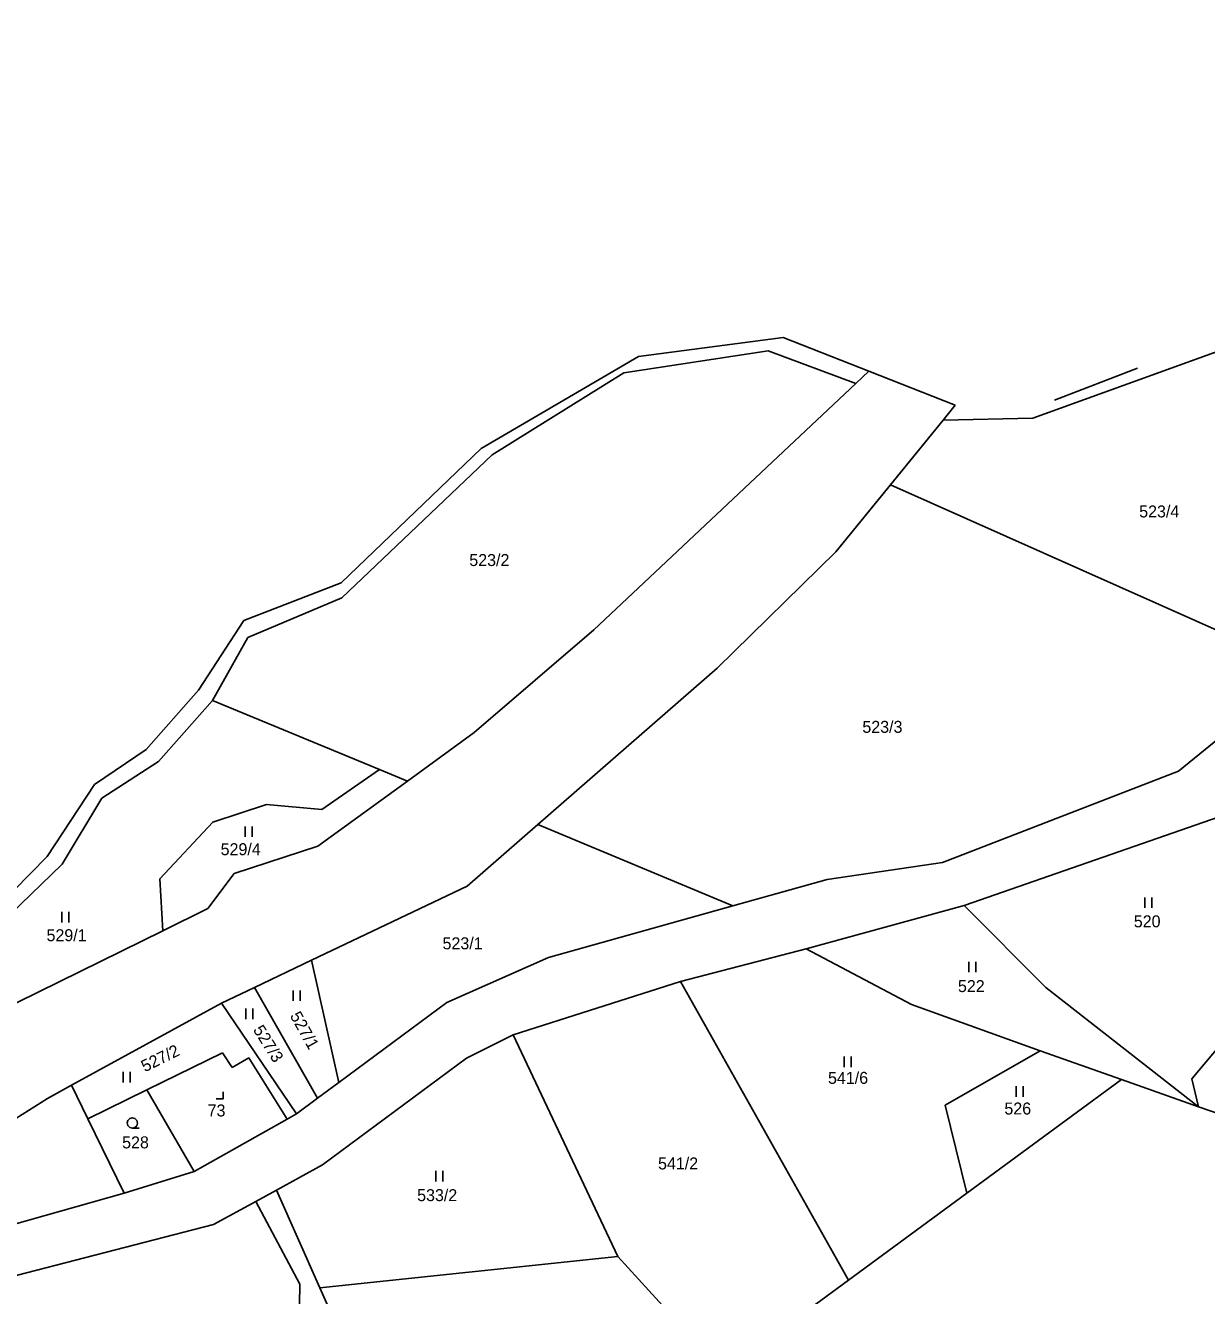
# Model space of a CAD drawing. Extents: x -580551 to -575069, y -1073031 to -1067931.
# Drawn here: x -578084.3 to -577916.6, y -1070422.6 to -1070242.2 of the extents above; entities that cross this region are included whole.
import ezdxf

# ---------------------------------------------------------------- set-up
doc = ezdxf.new("R2010")
doc.units = 0
for name, color, linetype in [('Druh pozemku', 7, 'Continuous'), ('Katastrální hranice', 7, 'Continuous'), ('Parcela', 7, 'Continuous'), ('Parcelní číslo', 7, 'Continuous'), ('Parcelní číslo_stavba', 7, 'Continuous'), ('SR - hranice státu', 7, 'Continuous'), ('Vrstva 6', 7, 'Continuous')]:
    doc.layers.add(name, color=color, linetype=linetype)

msp = doc.modelspace()

# ---------------------------------------------------------------- linework, layer by layer
at = {"layer": 'Druh pozemku'}
for p, q in [((-578053.09, -1070355.96), (-578053.09, -1070357.46)), ((-578052.09, -1070357.46), (-578052.09, -1070355.96)), ((-577925.41, -1070366.04), (-577925.41, -1070367.54)), ((-577924.41, -1070367.54), (-577924.41, -1070366.04)), ((-578079.11, -1070368.1), (-578079.11, -1070369.6)), ((-578078.11, -1070369.6), (-578078.11, -1070368.1)), ((-577950.39, -1070375.17), (-577950.39, -1070376.67)), ((-577949.39, -1070376.67), (-577949.39, -1070375.17)), ((-578046.26, -1070379.24), (-578046.26, -1070380.74)), ((-578045.26, -1070380.74), (-578045.26, -1070379.24)), ((-578052.98, -1070381.83), (-578052.98, -1070383.33)), ((-578051.98, -1070383.33), (-578051.98, -1070381.83)), ((-577968.09, -1070388.64), (-577968.09, -1070390.14)), ((-577967.09, -1070390.14), (-577967.09, -1070388.64)), ((-578070.39, -1070390.8), (-578070.39, -1070392.3)), ((-578069.39, -1070392.3), (-578069.39, -1070390.8)), ((-577943.68, -1070392.85), (-577943.68, -1070394.35)), ((-577942.68, -1070394.35), (-577942.68, -1070392.85)), ((-578026.05, -1070404.85), (-578026.05, -1070406.35)), ((-578025.05, -1070406.35), (-578025.05, -1070404.85))]:
    msp.add_line(p, q, dxfattribs=at)
for points in [[(-578057.21, -1070394.62), (-578056.21, -1070394.62), (-578056.21, -1070393.62)], [(-578069.1, -1070398.8), (-578069.48, -1070398.7), (-578069.75, -1070398.43), (-578069.85, -1070398.06), (-578069.75, -1070397.69), (-578069.48, -1070397.42), (-578069.11, -1070397.32), (-578068.74, -1070397.42), (-578068.47, -1070397.69), (-578068.37, -1070398.07), (-578068.47, -1070398.45), (-578068.74, -1070398.72), (-578069.12, -1070398.82), (-578068.12, -1070398.82)]]:
    msp.add_lwpolyline(points, dxfattribs=at)
at = {"layer": 'Katastrální hranice'}
for p, q in [((-577997.25, -1070289.24), (-577976.71, -1070286.54)), ((-577976.71, -1070286.54), (-577964.57, -1070291.33)), ((-578019.61, -1070302.3), (-577997.25, -1070289.24)), ((-577938.2, -1070295.46), (-577926.42, -1070290.9)), ((-577964.57, -1070291.33), (-577952.33, -1070296.15)), ((-578039.45, -1070321.4), (-578019.61, -1070302.3)), ((-578053.29, -1070326.73), (-578039.45, -1070321.4)), ((-578059.73, -1070336.6), (-578053.29, -1070326.73)), ((-578067.12, -1070345.05), (-578059.73, -1070336.6)), ((-578074.46, -1070350), (-578067.12, -1070345.05)), ((-578081.21, -1070360.24), (-578074.46, -1070350)), ((-578090.07, -1070369.27), (-578081.21, -1070360.24))]:
    msp.add_line(p, q, dxfattribs=at)
at = {"layer": 'Parcela'}
for p, q in [((-577978.84, -1070288.44), (-577999.34, -1070291.58)), ((-577966.44, -1070293.09), (-577978.84, -1070288.44)), ((-577915.49, -1070288.69), (-577941.3, -1070298.02)), ((-577999.34, -1070291.58), (-578018.01, -1070303.19)), ((-577966.44, -1070293.09), (-577964.57, -1070291.33)), ((-578003.58, -1070328.05), (-577966.44, -1070293.09)), ((-577954.03, -1070298.29), (-577952.33, -1070296.15)), ((-577954.03, -1070298.29), (-577961.49, -1070307.45)), ((-577941.3, -1070298.02), (-577954.03, -1070298.29)), ((-578018.01, -1070303.19), (-578039.36, -1070323.53)), ((-577961.49, -1070307.45), (-577969.25, -1070316.96)), ((-577969.25, -1070316.96), (-577986.12, -1070333.51)), ((-578039.36, -1070323.53), (-578052.73, -1070329.14)), ((-578003.58, -1070328.05), (-578020.59, -1070342.62)), ((-578052.73, -1070329.14), (-578057.71, -1070338.11)), ((-577986.12, -1070333.51), (-578011.56, -1070355.7)), ((-577902.84, -1070333.65), (-577920.62, -1070348.1)), ((-578057.71, -1070338.11), (-578065.41, -1070346.75)), ((-578057.71, -1070338.11), (-578034, -1070347.9)), ((-578020.59, -1070342.62), (-578030.06, -1070349.53)), ((-578065.41, -1070346.75), (-578073.43, -1070351.93)), ((-578034, -1070347.9), (-578042.22, -1070353.58)), ((-578034, -1070347.9), (-578030.06, -1070349.53)), ((-577920.62, -1070348.1), (-577954.14, -1070361.11)), ((-578030.06, -1070349.53), (-578042.76, -1070358.79)), ((-578073.43, -1070351.93), (-578079.06, -1070361.34)), ((-578050.07, -1070352.87), (-578057.7, -1070355.36)), ((-578042.22, -1070353.58), (-578050.07, -1070352.87)), ((-577912.66, -1070353.85), (-577951.04, -1070367.2)), ((-578057.7, -1070355.36), (-578065.19, -1070363.4)), ((-578011.56, -1070355.7), (-578021.6, -1070364.46)), ((-578042.76, -1070358.79), (-578054.63, -1070362.67)), ((-578079.06, -1070361.34), (-578087.95, -1070369.9)), ((-577954.14, -1070361.11), (-577970.5, -1070363.51)), ((-578054.63, -1070362.67), (-578058.4, -1070367.63)), ((-578065.19, -1070363.4), (-578064.77, -1070370.78)), ((-578021.6, -1070364.46), (-578043.69, -1070374.97)), ((-577970.5, -1070363.51), (-577983.88, -1070367.25)), ((-578058.4, -1070367.63), (-578064.77, -1070370.78)), ((-577983.88, -1070367.25), (-578010.02, -1070374.56)), ((-577951.04, -1070367.2), (-577973.47, -1070373.34)), ((-577951.04, -1070367.2), (-577939.47, -1070378.85)), ((-578064.77, -1070370.78), (-578120.48, -1070398.15)), ((-577973.47, -1070373.34), (-577991.31, -1070377.97)), ((-577958.53, -1070381.26), (-577973.47, -1070373.34)), ((-578043.69, -1070374.97), (-578051.76, -1070378.81)), ((-578043.69, -1070374.97), (-578039.78, -1070392.32)), ((-578010.02, -1070374.56), (-578024.46, -1070380.95)), ((-578051.76, -1070378.81), (-578056.47, -1070381.05)), ((-578051.76, -1070378.81), (-578042.8, -1070394.56)), ((-578015.07, -1070385.54), (-577991.31, -1070377.97)), ((-577991.31, -1070377.97), (-577967.46, -1070420.37)), ((-577939.47, -1070378.85), (-577917.78, -1070395.75)), ((-578056.47, -1070381.05), (-578077.72, -1070392.71)), ((-578056.47, -1070381.05), (-578045.79, -1070396.78)), ((-578024.46, -1070380.95), (-578039.78, -1070392.32)), ((-577940.26, -1070387.84), (-577958.53, -1070381.26)), ((-577910.44, -1070381.87), (-577918.74, -1070391.82)), ((-578021.66, -1070388.85), (-578015.07, -1070385.54)), ((-578000.19, -1070417.03), (-578015.07, -1070385.54)), ((-578067.05, -1070393.37), (-578056.32, -1070388.12)), ((-578056.32, -1070388.12), (-578054.93, -1070390.21)), ((-577940.26, -1070387.84), (-577953.76, -1070395.54)), ((-577928.7, -1070391.91), (-577940.26, -1070387.84)), ((-578054.93, -1070390.21), (-578052.55, -1070388.81)), ((-578052.55, -1070388.81), (-578047.12, -1070397.54)), ((-578042.12, -1070403.99), (-578021.66, -1070388.85)), ((-577950.65, -1070408.02), (-577928.7, -1070391.91)), ((-577917.78, -1070395.75), (-577928.7, -1070391.91)), ((-577918.74, -1070391.82), (-577917.78, -1070395.75)), ((-578077.72, -1070392.71), (-578081.13, -1070394.58)), ((-578077.72, -1070392.71), (-578075.41, -1070397.46)), ((-578075.41, -1070397.46), (-578067.05, -1070393.37)), ((-578060.34, -1070404.97), (-578067.05, -1070393.37)), ((-578039.78, -1070392.32), (-578042.8, -1070394.56)), ((-578081.13, -1070394.58), (-578100.99, -1070407.13)), ((-578042.8, -1070394.56), (-578045.79, -1070396.78)), ((-577953.76, -1070395.54), (-577950.65, -1070408.02)), ((-578075.41, -1070397.46), (-578070.24, -1070408.05)), ((-578060.34, -1070404.97), (-578047.12, -1070397.54)), ((-578047.12, -1070397.54), (-578045.79, -1070396.78)), ((-577904.4, -1070400.46), (-577917.78, -1070395.75)), ((-578048.66, -1070407.59), (-578042.12, -1070403.99)), ((-578070.24, -1070408.05), (-578060.34, -1070404.97)), ((-578070.24, -1070408.05), (-578106.52, -1070418.22)), ((-578051.59, -1070409.2), (-578048.66, -1070407.59)), ((-578042.48, -1070421.46), (-578048.66, -1070407.59)), ((-577967.46, -1070420.37), (-577950.65, -1070408.02)), ((-578057.57, -1070412.49), (-578051.59, -1070409.2)), ((-578051.59, -1070409.2), (-578045.35, -1070420.96)), ((-578096.29, -1070422.48), (-578057.57, -1070412.49)), ((-578000.19, -1070417.03), (-578042.48, -1070421.46)), ((-577985.2, -1070433.39), (-578000.19, -1070417.03)), ((-578045.35, -1070420.96), (-578045.43, -1070426.94)), ((-577980.64, -1070430.04), (-577967.46, -1070420.37)), ((-578039.68, -1070427.74), (-578042.48, -1070421.46))]:
    msp.add_line(p, q, dxfattribs=at)
at = {"layer": 'SR - hranice státu'}
msp.add_line((-577920.62, -1070348.1), (-577902.84, -1070333.65), dxfattribs=at)
for points in [[(-577835.39, -1070242.25), (-577841.33, -1070246.2), (-577852.61, -1070255.75), (-577871.82, -1070268.96), (-577894.73, -1070281.19), (-577909.94, -1070286.69), (-577914.847, -1070288.464), (-577941.3, -1070298.02)], [(-577941.3, -1070298.02), (-577954.03, -1070298.29), (-577969.25, -1070316.96), (-577986.12, -1070333.51), (-578011.56, -1070355.7)], [(-578011.56, -1070355.7), (-578021.6, -1070364.46), (-578043.69, -1070374.97), (-578039.78, -1070392.32), (-578024.46, -1070380.95), (-578010.02, -1070374.56), (-577983.88, -1070367.25), (-577970.5, -1070363.51), (-577954.14, -1070361.11), (-577920.62, -1070348.1)], [(-578045.35, -1070420.96), (-578051.59, -1070409.2), (-578048.66, -1070407.59), (-578042.12, -1070403.99), (-578021.66, -1070388.85), (-578015.07, -1070385.54), (-577991.31, -1070377.97), (-577973.47, -1070373.34), (-577951.04, -1070367.2), (-577912.66, -1070353.85)], [(-578028.34, -1070441.78), (-578037.79, -1070433.58), (-578045.43, -1070426.94), (-578045.35, -1070420.96)]]:
    msp.add_lwpolyline(points, dxfattribs=at)
at = {"layer": 'Vrstva 6'}
for p, q in [((-577961.49, -1070307.45), (-577907.26, -1070331.67)), ((-578011.56, -1070355.7), (-577983.88, -1070367.25))]:
    msp.add_line(p, q, dxfattribs=at)

# ---------------------------------------------------------------- texts
at = {"layer": 'Parcelní číslo'}
for s, p in [('523/4', (-577926.202, -1070312.1)), ('523/2', (-578021.277, -1070319)), ('523/3', (-577965.489, -1070342.68)), ('529/4', (-578056.566, -1070360.05)), ('520', (-577926.964, -1070370.29)), ('529/1', (-578081.279, -1070372.26)), ('523/1', (-578025.075, -1070373.41)), ('522', (-577951.926, -1070379.48)), ('541/6', (-577970.364, -1070392.51)), ('526', (-577945.331, -1070396.86)), ('528', (-578070.548, -1070401.67)), ('541/2', (-577994.489, -1070404.66)), ('533/2', (-578028.679, -1070409.16))]:
    msp.add_text(s, height=1.7, dxfattribs=at).set_placement(p)
for s, rotation, p in [('527/1', 299.25586, (-578046.785, -1070382.843)), ('527/3', 302.34983, (-578052.03, -1070384.846)), ('527/2', 26.29876, (-578067.328, -1070390.892))]:
    msp.add_text(s, height=1.7, rotation=rotation, dxfattribs=at).set_placement(p)
at = {"layer": 'Parcelní číslo_stavba'}
msp.add_text('73', height=1.7, dxfattribs=at).set_placement((-578058.417, -1070397.14))

doc.saveas('drawing.dxf')
